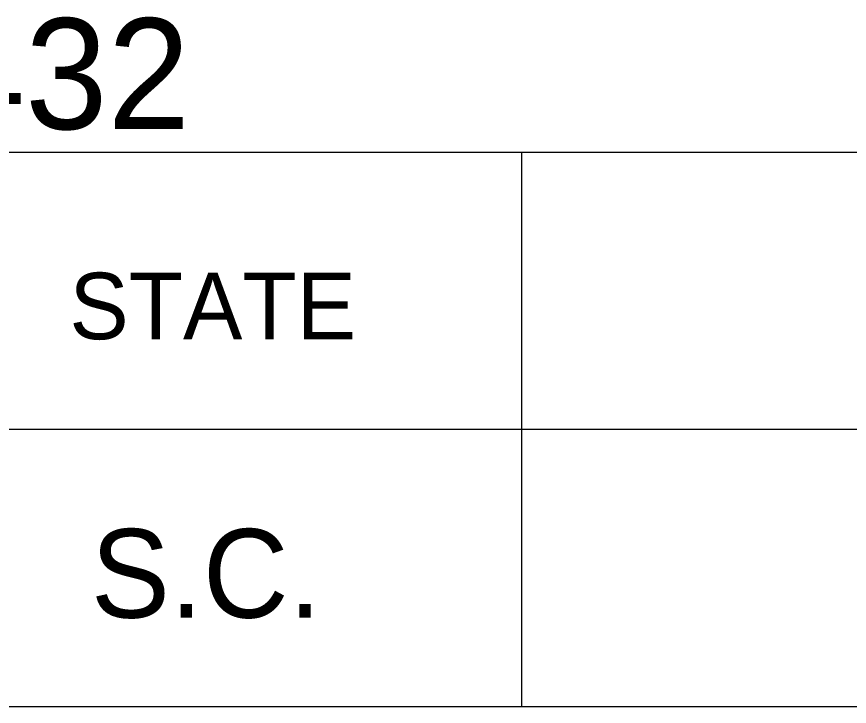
# Model space of a CAD drawing. Extents: x 1000 to 1162, y 999 to 8520.
# Drawn here: x 1136.81 to 1140.565, y 7080.046 to 7083.157 of the extents above; entities that cross this region are included whole.
import ezdxf

# ---------------------------------------------------------------- set-up
doc = ezdxf.new("R2010")
doc.units = 0
doc.layers.add('Level 20', color=7, linetype='Continuous')
doc.layers.add('Level 3', color=7, linetype='Continuous')

msp = doc.modelspace()

# ---------------------------------------------------------------- linework, layer by layer
at = {"layer": 'Level 3'}
for p, q in [((1133.055, 7082.5458), (1161.555, 7082.5458)), ((1133.055, 7082.5458), (1161.555, 7082.5458)), ((1133.055, 7082.5458), (1161.555, 7082.5458)), ((1133.055, 7082.5458), (1161.555, 7082.5458)), ((1133.055, 7082.5458), (1161.555, 7082.5458)), ((1133.055, 7082.5458), (1161.555, 7082.5458)), ((1133.055, 7082.5458), (1161.555, 7082.5458)), ((1133.055, 7082.5458), (1161.555, 7082.5458)), ((1133.055, 7082.5458), (1161.555, 7082.5458)), ((1133.055, 7082.5458), (1161.555, 7082.5458)), ((1133.055, 7082.5458), (1161.555, 7082.5458)), ((1133.055, 7082.5458), (1161.555, 7082.5458)), ((1133.055, 7082.5458), (1161.555, 7082.5458)), ((1133.055, 7082.5458), (1161.555, 7082.5458)), ((1133.055, 7082.5458), (1161.555, 7082.5458)), ((1133.055, 7082.5458), (1161.555, 7082.5458)), ((1133.055, 7082.5458), (1161.555, 7082.5458)), ((1133.055, 7082.5458), (1161.555, 7082.5458)), ((1133.055, 7082.5458), (1161.555, 7082.5458)), ((1133.055, 7082.5458), (1161.555, 7082.5458)), ((1133.055, 7082.5458), (1161.555, 7082.5458)), ((1133.055, 7082.5458), (1161.555, 7082.5458)), ((1133.055, 7082.5458), (1161.555, 7082.5458)), ((1133.055, 7082.5458), (1161.555, 7082.5458)), ((1133.055, 7082.5458), (1161.555, 7082.5458)), ((1133.055, 7082.5458), (1161.555, 7082.5458)), ((1133.055, 7082.5458), (1161.555, 7082.5458)), ((1133.055, 7082.5458), (1161.555, 7082.5458)), ((1133.055, 7082.5458), (1161.555, 7082.5458)), ((1133.055, 7082.5458), (1161.555, 7082.5458)), ((1133.055, 7082.5458), (1161.555, 7082.5458)), ((1133.055, 7082.5458), (1161.555, 7082.5458)), ((1133.055, 7082.5458), (1161.555, 7082.5458)), ((1133.055, 7082.5458), (1161.555, 7082.5458)), ((1133.055, 7082.5458), (1161.555, 7082.5458)), ((1133.055, 7082.5458), (1161.555, 7082.5458)), ((1133.055, 7082.5458), (1161.555, 7082.5458)), ((1133.055, 7082.5458), (1161.555, 7082.5458)), ((1133.055, 7082.5458), (1161.555, 7082.5458)), ((1133.055, 7082.5458), (1161.555, 7082.5458)), ((1133.055, 7082.5458), (1161.555, 7082.5458)), ((1133.055, 7082.5458), (1161.555, 7082.5458)), ((1133.055, 7082.5458), (1161.555, 7082.5458)), ((1133.055, 7082.5458), (1161.555, 7082.5458)), ((1133.055, 7082.5458), (1161.555, 7082.5458)), ((1133.055, 7082.5458), (1161.555, 7082.5458)), ((1133.055, 7082.5458), (1161.555, 7082.5458)), ((1133.055, 7082.5458), (1161.555, 7082.5458)), ((1133.055, 7082.5458), (1161.555, 7082.5458)), ((1133.055, 7082.5458), (1161.555, 7082.5458)), ((1133.055, 7082.5458), (1161.555, 7082.5458)), ((1139.0868, 7082.5458), (1139.0868, 7080.0458)), ((1139.0868, 7082.5458), (1139.0868, 7080.0458)), ((1139.0868, 7082.5458), (1139.0868, 7080.0458)), ((1139.0868, 7082.5458), (1139.0868, 7080.0458)), ((1139.0868, 7082.5458), (1139.0868, 7080.0458)), ((1139.0868, 7082.5458), (1139.0868, 7080.0458)), ((1139.0868, 7082.5458), (1139.0868, 7080.0458)), ((1139.0868, 7082.5458), (1139.0868, 7080.0458)), ((1139.0868, 7082.5458), (1139.0868, 7080.0458)), ((1139.0868, 7082.5458), (1139.0868, 7080.0458)), ((1139.0868, 7082.5458), (1139.0868, 7080.0458)), ((1139.0868, 7082.5458), (1139.0868, 7080.0458)), ((1139.0868, 7082.5458), (1139.0868, 7080.0458)), ((1139.0868, 7082.5458), (1139.0868, 7080.0458)), ((1139.0868, 7082.5458), (1139.0868, 7080.0458)), ((1139.0868, 7082.5458), (1139.0868, 7080.0458)), ((1139.0868, 7082.5458), (1139.0868, 7080.0458)), ((1139.0868, 7082.5458), (1139.0868, 7080.0458)), ((1139.0868, 7082.5458), (1139.0868, 7080.0458)), ((1139.0868, 7082.5458), (1139.0868, 7080.0458)), ((1139.0868, 7082.5458), (1139.0868, 7080.0458)), ((1139.0868, 7082.5458), (1139.0868, 7080.0458)), ((1139.0868, 7082.5458), (1139.0868, 7080.0458)), ((1139.0868, 7082.5458), (1139.0868, 7080.0458)), ((1139.0868, 7082.5458), (1139.0868, 7080.0458)), ((1139.0868, 7082.5458), (1139.0868, 7080.0458)), ((1139.0868, 7082.5458), (1139.0868, 7080.0458)), ((1139.0868, 7082.5458), (1139.0868, 7080.0458)), ((1139.0868, 7082.5458), (1139.0868, 7080.0458)), ((1139.0868, 7082.5458), (1139.0868, 7080.0458)), ((1139.0868, 7082.5458), (1139.0868, 7080.0458)), ((1139.0868, 7082.5458), (1139.0868, 7080.0458)), ((1139.0868, 7082.5458), (1139.0868, 7080.0458)), ((1139.0868, 7082.5458), (1139.0868, 7080.0458)), ((1139.0868, 7082.5458), (1139.0868, 7080.0458)), ((1139.0868, 7082.5458), (1139.0868, 7080.0458)), ((1139.0868, 7082.5458), (1139.0868, 7080.0458)), ((1139.0868, 7082.5458), (1139.0868, 7080.0458)), ((1139.0868, 7082.5458), (1139.0868, 7080.0458)), ((1139.0868, 7082.5458), (1139.0868, 7080.0458)), ((1139.0868, 7082.5458), (1139.0868, 7080.0458)), ((1139.0868, 7082.5458), (1139.0868, 7080.0458)), ((1139.0868, 7082.5458), (1139.0868, 7080.0458)), ((1139.0868, 7082.5458), (1139.0868, 7080.0458)), ((1139.0868, 7082.5458), (1139.0868, 7080.0458)), ((1139.0868, 7082.5458), (1139.0868, 7080.0458)), ((1139.0868, 7082.5458), (1139.0868, 7080.0458)), ((1139.0868, 7082.5458), (1139.0868, 7080.0458)), ((1139.0868, 7082.5458), (1139.0868, 7080.0458)), ((1139.0868, 7082.5458), (1139.0868, 7080.0458)), ((1139.0868, 7082.5458), (1139.0868, 7080.0458)), ((1133.055, 7081.2958), (1161.555, 7081.2958)), ((1133.055, 7081.2958), (1161.555, 7081.2958)), ((1133.055, 7081.2958), (1161.555, 7081.2958)), ((1133.055, 7081.2958), (1161.555, 7081.2958)), ((1133.055, 7081.2958), (1161.555, 7081.2958)), ((1133.055, 7081.2958), (1161.555, 7081.2958)), ((1133.055, 7081.2958), (1161.555, 7081.2958)), ((1133.055, 7081.2958), (1161.555, 7081.2958)), ((1133.055, 7081.2958), (1161.555, 7081.2958)), ((1133.055, 7081.2958), (1161.555, 7081.2958)), ((1133.055, 7081.2958), (1161.555, 7081.2958)), ((1133.055, 7081.2958), (1161.555, 7081.2958)), ((1133.055, 7081.2958), (1161.555, 7081.2958)), ((1133.055, 7081.2958), (1161.555, 7081.2958)), ((1133.055, 7081.2958), (1161.555, 7081.2958)), ((1133.055, 7081.2958), (1161.555, 7081.2958)), ((1133.055, 7081.2958), (1161.555, 7081.2958)), ((1133.055, 7081.2958), (1161.555, 7081.2958)), ((1133.055, 7081.2958), (1161.555, 7081.2958)), ((1133.055, 7081.2958), (1161.555, 7081.2958)), ((1133.055, 7081.2958), (1161.555, 7081.2958)), ((1133.055, 7081.2958), (1161.555, 7081.2958)), ((1133.055, 7081.2958), (1161.555, 7081.2958)), ((1133.055, 7081.2958), (1161.555, 7081.2958)), ((1133.055, 7081.2958), (1161.555, 7081.2958)), ((1133.055, 7081.2958), (1161.555, 7081.2958)), ((1133.055, 7081.2958), (1161.555, 7081.2958)), ((1133.055, 7081.2958), (1161.555, 7081.2958)), ((1133.055, 7081.2958), (1161.555, 7081.2958)), ((1133.055, 7081.2958), (1161.555, 7081.2958)), ((1133.055, 7081.2958), (1161.555, 7081.2958)), ((1133.055, 7081.2958), (1161.555, 7081.2958)), ((1133.055, 7081.2958), (1161.555, 7081.2958)), ((1133.055, 7081.2958), (1161.555, 7081.2958)), ((1133.055, 7081.2958), (1161.555, 7081.2958)), ((1133.055, 7081.2958), (1161.555, 7081.2958)), ((1133.055, 7081.2958), (1161.555, 7081.2958)), ((1133.055, 7081.2958), (1161.555, 7081.2958)), ((1133.055, 7081.2958), (1161.555, 7081.2958)), ((1133.055, 7081.2958), (1161.555, 7081.2958)), ((1133.055, 7081.2958), (1161.555, 7081.2958)), ((1133.055, 7081.2958), (1161.555, 7081.2958)), ((1133.055, 7081.2958), (1161.555, 7081.2958)), ((1133.055, 7081.2958), (1161.555, 7081.2958)), ((1133.055, 7081.2958), (1161.555, 7081.2958)), ((1133.055, 7081.2958), (1161.555, 7081.2958)), ((1133.055, 7081.2958), (1161.555, 7081.2958)), ((1133.055, 7081.2958), (1161.555, 7081.2958)), ((1133.055, 7081.2958), (1161.555, 7081.2958)), ((1133.055, 7081.2958), (1161.555, 7081.2958)), ((1133.055, 7081.2958), (1161.555, 7081.2958)), ((1133.055, 7080.0458), (1161.555, 7080.0458)), ((1133.055, 7080.0458), (1161.555, 7080.0458)), ((1133.055, 7080.0458), (1161.555, 7080.0458)), ((1133.055, 7080.0458), (1161.555, 7080.0458)), ((1133.055, 7080.0458), (1161.555, 7080.0458)), ((1133.055, 7080.0458), (1161.555, 7080.0458)), ((1133.055, 7080.0458), (1161.555, 7080.0458)), ((1133.055, 7080.0458), (1161.555, 7080.0458)), ((1133.055, 7080.0458), (1161.555, 7080.0458)), ((1133.055, 7080.0458), (1161.555, 7080.0458)), ((1133.055, 7080.0458), (1161.555, 7080.0458)), ((1133.055, 7080.0458), (1161.555, 7080.0458)), ((1133.055, 7080.0458), (1161.555, 7080.0458)), ((1133.055, 7080.0458), (1161.555, 7080.0458)), ((1133.055, 7080.0458), (1161.555, 7080.0458)), ((1133.055, 7080.0458), (1161.555, 7080.0458)), ((1133.055, 7080.0458), (1161.555, 7080.0458)), ((1133.055, 7080.0458), (1161.555, 7080.0458)), ((1133.055, 7080.0458), (1161.555, 7080.0458)), ((1133.055, 7080.0458), (1161.555, 7080.0458)), ((1133.055, 7080.0458), (1161.555, 7080.0458)), ((1133.055, 7080.0458), (1161.555, 7080.0458)), ((1133.055, 7080.0458), (1161.555, 7080.0458)), ((1133.055, 7080.0458), (1161.555, 7080.0458)), ((1133.055, 7080.0458), (1161.555, 7080.0458)), ((1133.055, 7080.0458), (1161.555, 7080.0458)), ((1133.055, 7080.0458), (1161.555, 7080.0458)), ((1133.055, 7080.0458), (1161.555, 7080.0458)), ((1133.055, 7080.0458), (1161.555, 7080.0458)), ((1133.055, 7080.0458), (1161.555, 7080.0458)), ((1133.055, 7080.0458), (1161.555, 7080.0458)), ((1133.055, 7080.0458), (1161.555, 7080.0458)), ((1133.055, 7080.0458), (1161.555, 7080.0458)), ((1133.055, 7080.0458), (1161.555, 7080.0458)), ((1133.055, 7080.0458), (1161.555, 7080.0458)), ((1133.055, 7080.0458), (1161.555, 7080.0458)), ((1133.055, 7080.0458), (1161.555, 7080.0458)), ((1133.055, 7080.0458), (1161.555, 7080.0458)), ((1133.055, 7080.0458), (1161.555, 7080.0458)), ((1133.055, 7080.0458), (1161.555, 7080.0458)), ((1133.055, 7080.0458), (1161.555, 7080.0458)), ((1133.055, 7080.0458), (1161.555, 7080.0458)), ((1133.055, 7080.0458), (1161.555, 7080.0458)), ((1133.055, 7080.0458), (1161.555, 7080.0458)), ((1133.055, 7080.0458), (1161.555, 7080.0458)), ((1133.055, 7080.0458), (1161.555, 7080.0458)), ((1133.055, 7080.0458), (1161.555, 7080.0458)), ((1133.055, 7080.0458), (1161.555, 7080.0458)), ((1133.055, 7080.0458), (1161.555, 7080.0458)), ((1133.055, 7080.0458), (1161.555, 7080.0458)), ((1133.055, 7080.0458), (1161.555, 7080.0458))]:
    msp.add_line(p, q, dxfattribs=at)

# ---------------------------------------------------------------- texts
at = {"layer": 'Level 20'}
msp.add_text('PIN NO. 26432', height=0.5, dxfattribs=at).set_placement((1133.0578, 7082.65))
at = {"layer": 'Level 3'}
for s, height, p in [('STATE', 0.3, (1137.0478, 7081.7021)), ('STATE', 0.3, (1137.0478, 7081.7021)), ('STATE', 0.3, (1137.0478, 7081.7021)), ('STATE', 0.3, (1137.0478, 7081.7021)), ('STATE', 0.3, (1137.0478, 7081.7021)), ('STATE', 0.3, (1137.0478, 7081.7021)), ('STATE', 0.3, (1137.0478, 7081.7021)), ('STATE', 0.3, (1137.0478, 7081.7021)), ('STATE', 0.3, (1137.0478, 7081.7021)), ('STATE', 0.3, (1137.0478, 7081.7021)), ('STATE', 0.3, (1137.0478, 7081.7021)), ('STATE', 0.3, (1137.0478, 7081.7021)), ('STATE', 0.3, (1137.0478, 7081.7021)), ('STATE', 0.3, (1137.0478, 7081.7021)), ('STATE', 0.3, (1137.0478, 7081.7021)), ('STATE', 0.3, (1137.0478, 7081.7021)), ('STATE', 0.3, (1137.0478, 7081.7021)), ('STATE', 0.3, (1137.0478, 7081.7021)), ('STATE', 0.3, (1137.0478, 7081.7021)), ('STATE', 0.3, (1137.0478, 7081.7021)), ('STATE', 0.3, (1137.0478, 7081.7021)), ('STATE', 0.3, (1137.0478, 7081.7021)), ('STATE', 0.3, (1137.0478, 7081.7021)), ('STATE', 0.3, (1137.0478, 7081.7021)), ('STATE', 0.3, (1137.0478, 7081.7021)), ('STATE', 0.3, (1137.0478, 7081.7021)), ('STATE', 0.3, (1137.0478, 7081.7021)), ('STATE', 0.3, (1137.0478, 7081.7021)), ('STATE', 0.3, (1137.0478, 7081.7021)), ('STATE', 0.3, (1137.0478, 7081.7021)), ('STATE', 0.3, (1137.0478, 7081.7021)), ('STATE', 0.3, (1137.0478, 7081.7021)), ('STATE', 0.3, (1137.0478, 7081.7021)), ('STATE', 0.3, (1137.0478, 7081.7021)), ('STATE', 0.3, (1137.0478, 7081.7021)), ('STATE', 0.3, (1137.0478, 7081.7021)), ('STATE', 0.3, (1137.0478, 7081.7021)), ('STATE', 0.3, (1137.0478, 7081.7021)), ('STATE', 0.3, (1137.0478, 7081.7021)), ('STATE', 0.3, (1137.0478, 7081.7021)), ('STATE', 0.3, (1137.0478, 7081.7021)), ('STATE', 0.3, (1137.0478, 7081.7021)), ('STATE', 0.3, (1137.0478, 7081.7021)), ('STATE', 0.3, (1137.0478, 7081.7021)), ('STATE', 0.3, (1137.0478, 7081.7021)), ('STATE', 0.3, (1137.0478, 7081.7021)), ('STATE', 0.3, (1137.0478, 7081.7021)), ('STATE', 0.3, (1137.0478, 7081.7021)), ('STATE', 0.3, (1137.0478, 7081.7021)), ('STATE', 0.3, (1137.0478, 7081.7021)), ('STATE', 0.3, (1137.0478, 7081.7021)), ('S.C.', 0.39999, (1137.1448, 7080.4458)), ('S.C.', 0.39999, (1137.1448, 7080.4458)), ('S.C.', 0.39999, (1137.1448, 7080.4458)), ('S.C.', 0.39999, (1137.1448, 7080.4458)), ('S.C.', 0.39999, (1137.1448, 7080.4458)), ('S.C.', 0.39999, (1137.1448, 7080.4458)), ('S.C.', 0.39999, (1137.1448, 7080.4458)), ('S.C.', 0.39999, (1137.1448, 7080.4458)), ('S.C.', 0.39999, (1137.1448, 7080.4458)), ('S.C.', 0.39999, (1137.1448, 7080.4458)), ('S.C.', 0.39999, (1137.1448, 7080.4458)), ('S.C.', 0.39999, (1137.1448, 7080.4458)), ('S.C.', 0.39999, (1137.1448, 7080.4458)), ('S.C.', 0.39999, (1137.1448, 7080.4458)), ('S.C.', 0.39999, (1137.1448, 7080.4458)), ('S.C.', 0.39999, (1137.1448, 7080.4458)), ('S.C.', 0.39999, (1137.1448, 7080.4458)), ('S.C.', 0.39999, (1137.1448, 7080.4458)), ('S.C.', 0.39999, (1137.1448, 7080.4458)), ('S.C.', 0.39999, (1137.1448, 7080.4458)), ('S.C.', 0.39999, (1137.1448, 7080.4458)), ('S.C.', 0.39999, (1137.1448, 7080.4458)), ('S.C.', 0.39999, (1137.1448, 7080.4458)), ('S.C.', 0.39999, (1137.1448, 7080.4458)), ('S.C.', 0.39999, (1137.1448, 7080.4458)), ('S.C.', 0.39999, (1137.1448, 7080.4458)), ('S.C.', 0.39999, (1137.1448, 7080.4458)), ('S.C.', 0.39999, (1137.1448, 7080.4458)), ('S.C.', 0.39999, (1137.1448, 7080.4458)), ('S.C.', 0.39999, (1137.1448, 7080.4458)), ('S.C.', 0.39999, (1137.1448, 7080.4458)), ('S.C.', 0.39999, (1137.1448, 7080.4458)), ('S.C.', 0.39999, (1137.1448, 7080.4458)), ('S.C.', 0.39999, (1137.1448, 7080.4458)), ('S.C.', 0.39999, (1137.1448, 7080.4458)), ('S.C.', 0.39999, (1137.1448, 7080.4458)), ('S.C.', 0.39999, (1137.1448, 7080.4458)), ('S.C.', 0.39999, (1137.1448, 7080.4458)), ('S.C.', 0.39999, (1137.1448, 7080.4458)), ('S.C.', 0.39999, (1137.1448, 7080.4458)), ('S.C.', 0.39999, (1137.1448, 7080.4458)), ('S.C.', 0.39999, (1137.1448, 7080.4458)), ('S.C.', 0.39999, (1137.1448, 7080.4458)), ('S.C.', 0.39999, (1137.1448, 7080.4458)), ('S.C.', 0.39999, (1137.1448, 7080.4458)), ('S.C.', 0.39999, (1137.1448, 7080.4458)), ('S.C.', 0.39999, (1137.1448, 7080.4458)), ('S.C.', 0.39999, (1137.1448, 7080.4458)), ('S.C.', 0.39999, (1137.1448, 7080.4458)), ('S.C.', 0.39999, (1137.1448, 7080.4458)), ('S.C.', 0.39999, (1137.1448, 7080.4458))]:
    msp.add_text(s, height=height, dxfattribs=at).set_placement(p)

doc.saveas('drawing.dxf')
